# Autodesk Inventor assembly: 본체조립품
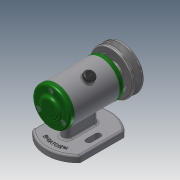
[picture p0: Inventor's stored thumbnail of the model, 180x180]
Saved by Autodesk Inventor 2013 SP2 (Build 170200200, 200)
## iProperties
Created: 2022-02
Part Number: 본체조립품
Document SubType Name: Assembly
Designer: a
Author: a
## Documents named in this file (14)
- C:\Users\a\Desktop\720206V1008\본체조립품.iam
- C:\Users\a\Desktop\720206V1008\본체.ipt
- C:\Users\a\Desktop\720206V1008\V벨트풀리.ipt
- C:\Users\a\Desktop\720206V1008\고무 캡.ipt
- C:\Users\a\Desktop\720206V1008\너트 M8.ipt
- C:\Users\a\Desktop\720206V1008\뒤커버.ipt
- C:\Users\a\Desktop\720206V1008\베어링 6002.ipt
- C:\Users\a\Desktop\720206V1008\볼트 M4 x 10.ipt
- C:\Users\a\Desktop\720206V1008\스프링와셔 8.ipt
- C:\Users\a\Desktop\720206V1008\앞커버.ipt
- C:\Users\a\Desktop\720206V1008\오일 실 15 x 25 x 7.ipt
- C:\Users\a\Desktop\720206V1008\축.ipt
- C:\Users\a\Desktop\720206V1008\키 3 x 3 x 12.ipt
- C:\Users\a\Desktop\720206V1008\평와셔 8 x 17.ipt
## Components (2 placed, 2 different names)
1. V벨트풀리:1
2. 고무 캡:1
